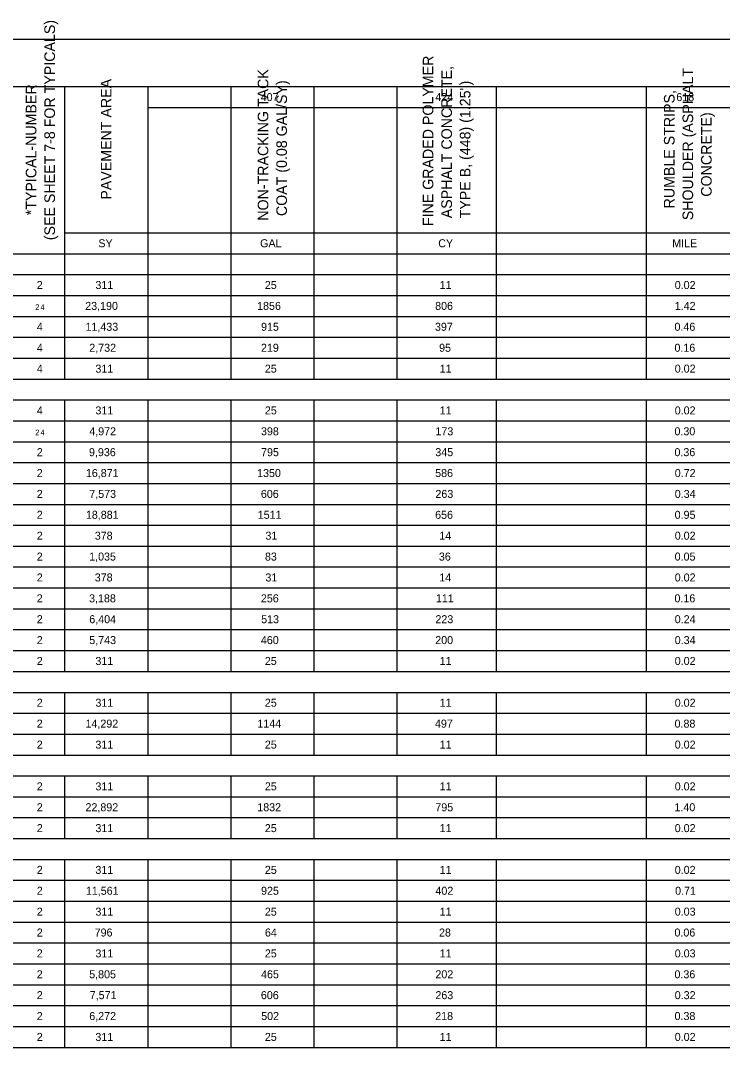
# Model space of a CAD drawing. Extents: x 0 to 34, y 0 to 22.3.
# Drawn here: x 9.54 to 16.97, y 11.14 to 22.2 of the extents above; entities that cross this region are included whole.
import ezdxf

# ---------------------------------------------------------------- set-up
doc = ezdxf.new("R2010")
doc.units = 0
for name, color, linetype in [('SH_Border', 7, 'Continuous'), ('SH_Cut_Line', 7, 'Continuous'), ('SH_Text', 7, 'Continuous')]:
    doc.layers.add(name, color=color, linetype=linetype)

msp = doc.modelspace()

# ---------------------------------------------------------------- linework, layer by layer
at = {"layer": 'SH_Border'}
msp.add_lwpolyline([(1.5, 21.5), (33.5, 21.5), (33.5, 0.5), (1.5, 0.5)], close=True, dxfattribs=at)
at = {"layer": 'SH_Cut_Line'}
msp.add_lwpolyline([(0, 0), (34, 0), (34, 22), (0, 22)], close=True, dxfattribs=at)
at = {"layer": 'SH_Text'}
for p, q in [((1.5, 21.5), (32, 21.5)), ((10.005, 21.5), (10.005, 18.405)), ((10.885, 21.5), (10.885, 18.405)), ((11.764, 21.5), (11.764, 18.405)), ((12.644, 21.5), (12.644, 18.405)), ((13.524, 21.5), (13.524, 18.405)), ((14.575, 21.5), (14.575, 18.405)), ((16.163, 21.5), (16.163, 18.405)), ((10.885, 21.279), (26.721, 21.279)), ((10.005, 19.953), (32, 19.953)), ((1.5, 19.732), (32, 19.732)), ((1.5, 19.511), (32, 19.511)), ((1.5, 19.289), (32, 19.289)), ((1.5, 19.068), (32, 19.068)), ((1.5, 18.847), (32, 18.847)), ((1.5, 18.626), (32, 18.626)), ((1.5, 18.405), (32, 18.405)), ((1.5, 18.184), (32, 18.184)), ((10.005, 18.184), (10.005, 15.311)), ((10.885, 18.184), (10.885, 15.311)), ((11.764, 18.184), (11.764, 15.311)), ((12.644, 18.184), (12.644, 15.311)), ((13.524, 18.184), (13.524, 15.311)), ((14.575, 18.184), (14.575, 15.311)), ((16.163, 18.184), (16.163, 15.311)), ((1.5, 17.963), (32, 17.963)), ((1.5, 17.742), (32, 17.742)), ((1.5, 17.521), (32, 17.521)), ((1.5, 17.3), (32, 17.3)), ((1.5, 17.079), (32, 17.079)), ((1.5, 16.858), (32, 16.858)), ((1.5, 16.637), (32, 16.637)), ((1.5, 16.416), (32, 16.416)), ((1.5, 16.195), (32, 16.195)), ((1.5, 15.974), (32, 15.974)), ((1.5, 15.753), (32, 15.753)), ((1.5, 15.532), (32, 15.532)), ((1.5, 15.311), (32, 15.311)), ((1.5, 15.089), (32, 15.089)), ((10.005, 15.089), (10.005, 14.426)), ((10.885, 15.089), (10.885, 14.426)), ((11.764, 15.089), (11.764, 14.426)), ((12.644, 15.089), (12.644, 14.426)), ((13.524, 15.089), (13.524, 14.426)), ((14.575, 15.089), (14.575, 14.426)), ((16.163, 15.089), (16.163, 14.426)), ((1.5, 14.868), (32, 14.868)), ((1.5, 14.647), (32, 14.647)), ((1.5, 14.426), (32, 14.426)), ((1.5, 14.205), (32, 14.205)), ((10.005, 14.205), (10.005, 13.542)), ((10.885, 14.205), (10.885, 13.542)), ((11.764, 14.205), (11.764, 13.542)), ((12.644, 14.205), (12.644, 13.542)), ((13.524, 14.205), (13.524, 13.542)), ((14.575, 14.205), (14.575, 13.542)), ((16.163, 14.205), (16.163, 13.542)), ((1.5, 13.984), (32, 13.984)), ((1.5, 13.763), (32, 13.763)), ((1.5, 13.542), (32, 13.542)), ((1.5, 13.321), (32, 13.321)), ((10.005, 13.321), (10.005, 11.332)), ((10.885, 13.321), (10.885, 11.332)), ((11.764, 13.321), (11.764, 11.332)), ((12.644, 13.321), (12.644, 11.332)), ((13.524, 13.321), (13.524, 11.332)), ((14.575, 13.321), (14.575, 11.332)), ((16.163, 13.321), (16.163, 11.332)), ((1.5, 13.1), (32, 13.1)), ((1.5, 12.879), (32, 12.879)), ((1.5, 12.658), (32, 12.658)), ((1.5, 12.437), (32, 12.437)), ((1.5, 12.216), (32, 12.216)), ((1.5, 11.995), (32, 11.995)), ((1.5, 11.774), (32, 11.774)), ((1.5, 11.553), (32, 11.553)), ((1.5, 11.332), (32, 11.332))]:
    msp.add_line(p, q, dxfattribs=at)

# ---------------------------------------------------------------- texts
for s, height, p in [('(SEE SHEET 7-8 FOR TYPICALS)', 0.11242, (9.903, 19.875)), ('FINE GRADED POLYMER ', 0.11242, (13.909, 20.024)), ('NON-TRACKING TACK ', 0.11242, (12.162, 20.081)), ('ASPHALT CONCRETE, ', 0.11242, (14.106, 20.107)), ('SHOULDER (ASPHALT ', 0.11242, (16.66, 20.086)), ('PAVEMENT AREA', 0.11242, (10.501, 20.304)), ('COAT (0.08 GAL/SY)', 0.11242, (12.359, 20.13)), ('TYPE B, (448) (1.25")', 0.11242, (14.302, 20.106)), ('*TYPICAL-NUMBER                                     ', 0.11242, (9.706, 20.138)), ('RUMBLE STRIPS, ', 0.11242, (16.463, 20.211)), ('CONCRETE)', 0.1124, (16.856, 20.335))]:
    msp.add_text(s, height=height, rotation=90, dxfattribs=at).set_placement(p)
for s, height, p in [('407', 0.0847, (12.081, 21.347)), ('424', 0.0847, (13.93, 21.347)), ('618', 0.0847, (16.482, 21.347)), ('SY', 0.0847, (10.362, 19.8)), ('GAL', 0.0847, (12.075, 19.8)), ('CY', 0.0847, (13.961, 19.8)), ('MILE', 0.0847, (16.438, 19.8)), ('2', 0.0847, (9.71, 19.358)), ('311', 0.0847, (10.331, 19.358)), ('25', 0.0847, (12.125, 19.358)), ('11', 0.0847, (13.976, 19.358)), ('0.02', 0.0847, (16.465, 19.358)), ('2', 0.0593, (9.694, 19.137)), ('4', 0.0593, (9.75, 19.137)), ('23,190', 0.0847, (10.223, 19.137)), ('1856', 0.0847, (12.043, 19.137)), ('806', 0.0847, (13.928, 19.137)), ('1.42', 0.0847, (16.465, 19.137)), ('4', 0.0847, (9.711, 18.916)), ('11,433', 0.0847, (10.226, 18.916)), ('915', 0.0847, (12.085, 18.916)), ('397', 0.0847, (13.926, 18.916)), ('0.46', 0.0847, (16.462, 18.916)), ('4', 0.0847, (9.711, 18.694)), ('2,732', 0.0847, (10.266, 18.694)), ('219', 0.0847, (12.084, 18.694)), ('95', 0.0847, (13.97, 18.694)), ('0.16', 0.0847, (16.462, 18.694)), ('4', 0.0847, (9.711, 18.473)), ('311', 0.0847, (10.331, 18.473)), ('25', 0.0847, (12.125, 18.473)), ('11', 0.0847, (13.976, 18.473)), ('0.02', 0.0847, (16.465, 18.473)), ('4', 0.0847, (9.711, 18.031)), ('311', 0.0847, (10.331, 18.031)), ('25', 0.0847, (12.125, 18.031)), ('11', 0.0847, (13.976, 18.031)), ('0.02', 0.0847, (16.465, 18.031)), ('2', 0.0593, (9.694, 17.811)), ('4', 0.0593, (9.75, 17.811)), ('4,972', 0.0847, (10.266, 17.81)), ('398', 0.0847, (12.084, 17.81)), ('173', 0.0847, (13.931, 17.81)), ('0.30', 0.0847, (16.462, 17.81)), ('2', 0.0847, (9.71, 17.589)), ('9,936', 0.0847, (10.263, 17.589)), ('795', 0.0847, (12.085, 17.589)), ('345', 0.0847, (13.93, 17.589)), ('0.36', 0.0847, (16.462, 17.589)), ('2', 0.0847, (9.71, 17.368)), ('16,871', 0.0847, (10.23, 17.368)), ('1350', 0.0847, (12.043, 17.368)), ('586', 0.0847, (13.928, 17.368)), ('0.72', 0.0847, (16.465, 17.368)), ('2', 0.0847, (9.71, 17.147)), ('7,573', 0.0847, (10.266, 17.147)), ('606', 0.0847, (12.083, 17.147)), ('263', 0.0847, (13.931, 17.147)), ('0.34', 0.0847, (16.465, 17.147)), ('2', 0.0847, (9.71, 16.926)), ('18,881', 0.0847, (10.23, 16.926)), ('1511', 0.0847, (12.05, 16.926)), ('656', 0.0847, (13.928, 16.926)), ('0.95', 0.0847, (16.464, 16.926)), ('2', 0.0847, (9.71, 16.705)), ('378', 0.0847, (10.324, 16.705)), ('31', 0.0847, (12.131, 16.705)), ('14', 0.0847, (13.972, 16.705)), ('0.02', 0.0847, (16.465, 16.705)), ('2', 0.0847, (9.71, 16.484)), ('1,035', 0.0847, (10.265, 16.484)), ('83', 0.0847, (12.126, 16.484)), ('36', 0.0847, (13.968, 16.484)), ('0.05', 0.0847, (16.464, 16.484)), ('2', 0.0847, (9.71, 16.263)), ('378', 0.0847, (10.324, 16.263)), ('31', 0.0847, (12.131, 16.263)), ('14', 0.0847, (13.972, 16.263)), ('0.02', 0.0847, (16.465, 16.263)), ('2', 0.0847, (9.71, 16.042)), ('3,188', 0.0847, (10.264, 16.042)), ('256', 0.0847, (12.083, 16.042)), ('111', 0.0847, (13.936, 16.042)), ('0.16', 0.0847, (16.462, 16.042)), ('2', 0.0847, (9.71, 15.821)), ('6,404', 0.0847, (10.266, 15.821)), ('513', 0.0847, (12.086, 15.821)), ('223', 0.0847, (13.931, 15.821)), ('0.24', 0.0847, (16.465, 15.821)), ('2', 0.0847, (9.71, 15.6)), ('5,743', 0.0847, (10.266, 15.6)), ('460', 0.0847, (12.083, 15.6)), ('200', 0.0847, (13.929, 15.6)), ('0.34', 0.0847, (16.465, 15.6)), ('2', 0.0847, (9.71, 15.379)), ('311', 0.0847, (10.331, 15.379)), ('25', 0.0847, (12.125, 15.379)), ('11', 0.0847, (13.976, 15.379)), ('0.02', 0.0847, (16.465, 15.379)), ('2', 0.0847, (9.71, 14.937)), ('311', 0.0847, (10.331, 14.937)), ('25', 0.0847, (12.125, 14.937)), ('11', 0.0847, (13.976, 14.937)), ('0.02', 0.0847, (16.465, 14.937)), ('2', 0.0847, (9.71, 14.716)), ('14,292', 0.0847, (10.226, 14.716)), ('1144', 0.0847, (12.046, 14.716)), ('497', 0.0847, (13.926, 14.716)), ('0.88', 0.0847, (16.463, 14.716)), ('2', 0.0847, (9.71, 14.494)), ('311', 0.0847, (10.331, 14.494)), ('25', 0.0847, (12.125, 14.494)), ('11', 0.0847, (13.976, 14.494)), ('0.02', 0.0847, (16.465, 14.494)), ('2', 0.0847, (9.71, 14.052)), ('311', 0.0847, (10.331, 14.052)), ('25', 0.0847, (12.125, 14.052)), ('11', 0.0847, (13.976, 14.052)), ('0.02', 0.0847, (16.465, 14.052)), ('2', 0.0847, (9.71, 13.831)), ('22,892', 0.0847, (10.226, 13.831)), ('1832', 0.0847, (12.045, 13.831)), ('795', 0.0847, (13.93, 13.831)), ('1.40', 0.0847, (16.462, 13.831)), ('2', 0.0847, (9.71, 13.61)), ('311', 0.0847, (10.331, 13.61)), ('25', 0.0847, (12.125, 13.61)), ('11', 0.0847, (13.976, 13.61)), ('0.02', 0.0847, (16.465, 13.61)), ('2', 0.0847, (9.71, 13.168)), ('311', 0.0847, (10.331, 13.168)), ('25', 0.0847, (12.125, 13.168)), ('11', 0.0847, (13.976, 13.168)), ('0.02', 0.0847, (16.465, 13.168)), ('2', 0.0847, (9.71, 12.947)), ('11,561', 0.0847, (10.23, 12.947)), ('925', 0.0847, (12.085, 12.947)), ('402', 0.0847, (13.931, 12.947)), ('0.71', 0.0847, (16.469, 12.947)), ('2', 0.0847, (9.71, 12.726)), ('311', 0.0847, (10.331, 12.726)), ('25', 0.0847, (12.125, 12.726)), ('11', 0.0847, (13.976, 12.726)), ('0.03', 0.0847, (16.465, 12.726)), ('2', 0.0847, (9.71, 12.505)), ('796', 0.0847, (10.323, 12.505)), ('64', 0.0847, (12.126, 12.505)), ('28', 0.0847, (13.969, 12.505)), ('0.06', 0.0847, (16.462, 12.505)), ('2', 0.0847, (9.71, 12.284)), ('311', 0.0847, (10.331, 12.284)), ('25', 0.0847, (12.125, 12.284)), ('11', 0.0847, (13.976, 12.284)), ('0.03', 0.0847, (16.465, 12.284)), ('2', 0.0847, (9.71, 12.063)), ('5,805', 0.0847, (10.265, 12.063)), ('465', 0.0847, (12.085, 12.063)), ('202', 0.0847, (13.931, 12.063)), ('0.36', 0.0847, (16.462, 12.063)), ('2', 0.0847, (9.71, 11.842)), ('7,571', 0.0847, (10.271, 11.842)), ('606', 0.0847, (12.083, 11.842)), ('263', 0.0847, (13.931, 11.842)), ('0.32', 0.0847, (16.465, 11.842)), ('2', 0.0847, (9.71, 11.621)), ('6,272', 0.0847, (10.266, 11.621)), ('502', 0.0847, (12.086, 11.621)), ('218', 0.0847, (13.929, 11.621)), ('0.38', 0.0847, (16.463, 11.621)), ('2', 0.0847, (9.71, 11.4)), ('311', 0.0847, (10.331, 11.4)), ('25', 0.0847, (12.125, 11.4)), ('11', 0.0847, (13.976, 11.4)), ('0.02', 0.0847, (16.465, 11.4))]:
    msp.add_text(s, height=height, dxfattribs=at).set_placement(p)

doc.saveas('drawing.dxf')
